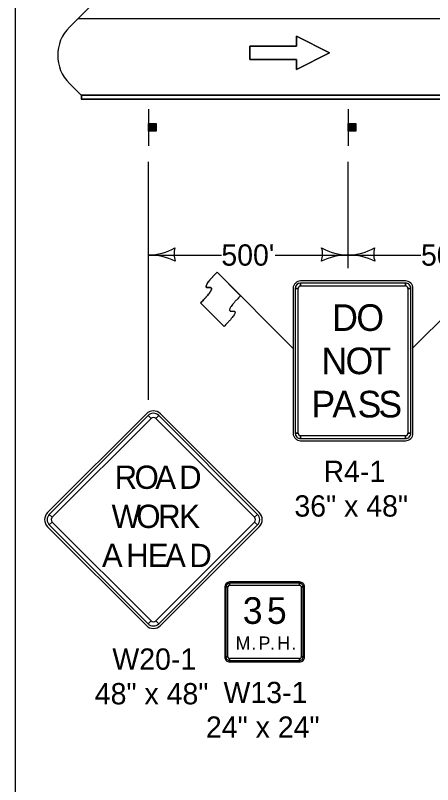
# Model space of a CAD drawing. Extents: x -2134934 to -2122394, y -2139046 to -2137036.
# Drawn here: x -2130232 to -2129918, y -2138183 to -2137605 of the extents above; entities that cross this region are included whole.
import ezdxf

# ---------------------------------------------------------------- set-up
doc = ezdxf.new("R2010")
doc.units = 0
for name, color, linetype in [('Barrier', 7, 'Continuous'), ('BridgeSuperStructureExisting', 7, 'Continuous'), ('Default', 7, 'Continuous'), ('DsnShtPlotIdentification', 7, 'Continuous'), ('TC_Barrier', 7, 'Continuous')]:
    doc.layers.add(name, color=color, linetype=linetype)

msp = doc.modelspace()

# ---------------------------------------------------------------- linework, layer by layer
at = {"layer": 'Barrier'}
for p, q in [((-2130023.11, -2137855.42), (-2130080.45, -2137798.12)), ((-2130080.45, -2137798.12), (-2130062.76, -2137815.8)), ((-2129933.82, -2137855.42), (-2129876.5, -2137798.11)), ((-2129938.87, -2137804.67), (-2130017.62, -2137804.67)), ((-2130017.62, -2137808.42), (-2130017.62, -2137806.23)), ((-2129938.87, -2137806.23), (-2129938.87, -2137808.42)), ((-2130023.24, -2137810.29), (-2130023.24, -2137919.04)), ((-2130021.68, -2137810.29), (-2130019.49, -2137810.29)), ((-2129936.99, -2137810.29), (-2129934.81, -2137810.29)), ((-2129933.24, -2137919.04), (-2129933.24, -2137810.29)), ((-2130075.13, -2137838.79), (-2130092.81, -2137821.12)), ((-2130133.53, -2137904.4), (-2130207.78, -2137978.64)), ((-2130132.2, -2137905.72), (-2130129.99, -2137907.93)), ((-2130126.46, -2137907.93), (-2130124.25, -2137905.72)), ((-2130048.68, -2137978.64), (-2130122.92, -2137904.4)), ((-2130019.49, -2137919.04), (-2130021.68, -2137919.04)), ((-2130017.62, -2137923.1), (-2130017.62, -2137920.91)), ((-2129938.87, -2137920.91), (-2129938.87, -2137923.1)), ((-2129934.81, -2137919.04), (-2129936.99, -2137919.04)), ((-2130017.62, -2137924.66), (-2129938.87, -2137924.66)), ((-2130204.24, -2137982.18), (-2130206.45, -2137979.97)), ((-2130050, -2137979.97), (-2130052.21, -2137982.18)), ((-2130206.45, -2137987.92), (-2130204.24, -2137985.71)), ((-2130052.21, -2137985.71), (-2130050, -2137987.92)), ((-2130207.78, -2137989.25), (-2130133.53, -2138063.5)), ((-2130122.92, -2138063.5), (-2130048.68, -2137989.25)), ((-2130018.46, -2138030.77), (-2130070.95, -2138030.77)), ((-2130070.95, -2138033.27), (-2130070.95, -2138031.71)), ((-2130018.46, -2138031.71), (-2130018.46, -2138033.27)), ((-2130074.7, -2138034.52), (-2130074.7, -2138087.02)), ((-2130073.77, -2138034.52), (-2130072.2, -2138034.52)), ((-2130017.21, -2138034.52), (-2130015.64, -2138034.52)), ((-2130014.71, -2138087.02), (-2130014.71, -2138034.52)), ((-2130129.99, -2138059.96), (-2130132.2, -2138062.17)), ((-2130124.25, -2138062.17), (-2130126.46, -2138059.96)), ((-2130072.2, -2138087.02), (-2130073.77, -2138087.02)), ((-2130070.95, -2138089.83), (-2130070.95, -2138088.27)), ((-2130070.95, -2138090.77), (-2130018.46, -2138090.77)), ((-2130018.46, -2138088.27), (-2130018.46, -2138089.83)), ((-2130015.64, -2138087.02), (-2130017.21, -2138087.02))]:
    msp.add_line(p, q, dxfattribs=at)
for points in [[(-2129938.87, -2137806.23), (-2130017.62, -2137806.23), (-2130017.62, -2137808.42), (-2129938.87, -2137808.42), (-2129938.87, -2137806.23)], [(-2130021.68, -2137810.29), (-2130021.68, -2137919.04), (-2130019.49, -2137919.04), (-2130019.49, -2137810.29), (-2130021.68, -2137810.29)], [(-2129934.81, -2137919.04), (-2129934.81, -2137810.29), (-2129936.99, -2137810.29), (-2129936.99, -2137919.04), (-2129934.81, -2137919.04)], [(-2130132.2, -2137905.72), (-2130206.45, -2137979.97), (-2130204.24, -2137982.18), (-2130129.99, -2137907.93), (-2130132.2, -2137905.72)], [(-2130050, -2137979.97), (-2130124.25, -2137905.72), (-2130126.46, -2137907.93), (-2130052.21, -2137982.18), (-2130050, -2137979.97)], [(-2130017.62, -2137923.1), (-2129938.87, -2137923.1), (-2129938.87, -2137920.91), (-2130017.62, -2137920.91), (-2130017.62, -2137923.1)], [(-2130206.45, -2137987.92), (-2130132.2, -2138062.17), (-2130129.99, -2138059.96), (-2130204.24, -2137985.71), (-2130206.45, -2137987.92)], [(-2130124.25, -2138062.17), (-2130050, -2137987.92), (-2130052.21, -2137985.71), (-2130126.46, -2138059.96), (-2130124.25, -2138062.17)], [(-2130018.46, -2138031.71), (-2130070.95, -2138031.71), (-2130070.95, -2138033.27), (-2130018.46, -2138033.27), (-2130018.46, -2138031.71)], [(-2130073.77, -2138034.52), (-2130073.77, -2138087.02), (-2130072.2, -2138087.02), (-2130072.2, -2138034.52), (-2130073.77, -2138034.52)], [(-2130015.64, -2138087.02), (-2130015.64, -2138034.52), (-2130017.21, -2138034.52), (-2130017.21, -2138087.02), (-2130015.64, -2138087.02)], [(-2130070.95, -2138089.83), (-2130018.46, -2138089.83), (-2130018.46, -2138088.27), (-2130070.95, -2138088.27), (-2130070.95, -2138089.83)]]:
    msp.add_lwpolyline(points, close=True, dxfattribs=at)
for centre, radius, start, end in [((-2130017.62, -2137810.29), 5.62, 90.00021, 179.99985), ((-2130017.62, -2137810.29), 4.06, 90.00021, 179.99985), ((-2129938.87, -2137810.29), 5.62, 0, 90.00021), ((-2129938.87, -2137810.29), 4.06, 0, 90.00021), ((-2130017.62, -2137810.29), 1.87, 90.00021, 179.99985), ((-2129938.87, -2137810.29), 1.87, 0, 90.00021), ((-2130128.23, -2137909.7), 7.5, 44.99999, 134.99974), ((-2130128.23, -2137909.7), 5.62, 44.99999, 134.99974), ((-2130128.23, -2137909.7), 2.5, 44.99999, 134.99974), ((-2130017.62, -2137919.04), 5.62, 179.99985, 270.00006), ((-2130017.62, -2137919.04), 4.06, 179.99985, 270.00006), ((-2130017.62, -2137919.04), 1.87, 179.99985, 270.00006), ((-2129938.87, -2137919.04), 5.62, 270.00006, 0.00027), ((-2129938.87, -2137919.04), 4.06, 270.00006, 0.00027), ((-2129938.87, -2137919.04), 1.87, 270.00006, 0.00027), ((-2130202.47, -2137983.95), 7.5, 134.99974, 224.99995), ((-2130202.47, -2137983.95), 5.62, 134.99974, 224.99995), ((-2130053.98, -2137983.95), 5.62, 315.00016, 44.9998), ((-2130053.98, -2137983.95), 7.5, 315.00016, 44.9998), ((-2130202.47, -2137983.95), 2.5, 134.99974, 224.99995), ((-2130053.98, -2137983.95), 2.5, 315.00016, 44.9998), ((-2130070.95, -2138034.52), 3.75, 90.00021, 179.99985), ((-2130070.95, -2138034.52), 2.81, 90.00021, 179.99985), ((-2130070.95, -2138034.52), 1.25, 90.00021, 179.99985), ((-2130018.46, -2138034.52), 3.75, 0, 90.00021), ((-2130018.46, -2138034.52), 2.81, 0, 90.00021), ((-2130018.46, -2138034.52), 1.25, 0, 90.00021), ((-2130128.23, -2138058.19), 5.62, 224.99995, 315.00016), ((-2130128.23, -2138058.19), 2.5, 224.99995, 315.00016), ((-2130128.23, -2138058.19), 7.5, 224.99995, 315.00016), ((-2130070.95, -2138087.02), 3.75, 179.99985, 270.00006), ((-2130070.95, -2138087.02), 2.81, 179.99985, 270.00006), ((-2130070.95, -2138087.02), 1.25, 179.99985, 270.00006), ((-2130018.46, -2138087.02), 3.75, 270.00006, 0.00027), ((-2130018.46, -2138087.02), 2.81, 270.00006, 0.00027), ((-2130018.46, -2138087.02), 1.25, 270.00006, 0.00027)]:
    msp.add_arc(centre, radius, start, end, dxfattribs=at)
for points in [[(-2130092.81, -2137821.12), (-2130080.44, -2137808.74), (-2130092.82, -2137810.51), (-2130080.45, -2137798.12)], [(-2130062.76, -2137815.8), (-2130075.13, -2137828.19), (-2130062.76, -2137826.41), (-2130075.13, -2137838.79)]]:
    msp.add_open_spline(points, degree=2, dxfattribs=at)
at = {"layer": 'BridgeSuperStructureExisting'}
for p, q in [((-2130173.78, -2137596.37), (-2130191.36, -2137613.95)), ((-2130173.79, -2137596.38), (-2130191.36, -2137613.95)), ((-2130191.36, -2137656.37), (-2130182.57, -2137665.16)), ((-2130191.36, -2137656.38), (-2130182.57, -2137665.16)), ((-2130182.57, -2137665.16), (-2128870.12, -2137665.16)), ((-2130131.95, -2137675.66), (-2130131.95, -2137703.16)), ((-2129981.95, -2137675.66), (-2129981.95, -2137703.16)), ((-2130131.54, -2137692.11), (-2130131.54, -2137686.52)), ((-2130131.26, -2137686.52), (-2130131.26, -2137692.11)), ((-2130130.99, -2137692.11), (-2130130.99, -2137686.52)), ((-2130130.73, -2137686.52), (-2130130.73, -2137692.11)), ((-2130130.51, -2137692.11), (-2130130.51, -2137686.52)), ((-2130130.3, -2137686.52), (-2130130.3, -2137692.11)), ((-2130129.96, -2137692.11), (-2130129.96, -2137686.52)), ((-2130129.7, -2137686.52), (-2130129.7, -2137692.11)), ((-2130129.47, -2137692.11), (-2130129.49, -2137686.52)), ((-2130129.16, -2137686.52), (-2130129.16, -2137692.11)), ((-2130128.78, -2137692.11), (-2130128.78, -2137686.52)), ((-2130128.35, -2137686.52), (-2130128.35, -2137692.11)), ((-2130128.12, -2137692.11), (-2130128.14, -2137686.52)), ((-2130127.71, -2137686.52), (-2130127.69, -2137692.11)), ((-2130127.49, -2137692.11), (-2130127.49, -2137686.52)), ((-2130127.17, -2137686.52), (-2130127.17, -2137692.11)), ((-2130126.94, -2137692.11), (-2130126.94, -2137686.52)), ((-2130126.62, -2137686.52), (-2130126.62, -2137692.11)), ((-2129981.54, -2137692.11), (-2129981.54, -2137686.52)), ((-2129981.26, -2137686.52), (-2129981.26, -2137692.11)), ((-2129980.99, -2137692.11), (-2129980.99, -2137686.52)), ((-2129980.73, -2137686.52), (-2129980.73, -2137692.11)), ((-2129980.51, -2137692.11), (-2129980.51, -2137686.52)), ((-2129980.3, -2137686.52), (-2129980.3, -2137692.11)), ((-2129979.96, -2137692.11), (-2129979.96, -2137686.52)), ((-2129979.7, -2137686.52), (-2129979.7, -2137692.11)), ((-2129979.47, -2137692.11), (-2129979.49, -2137686.52)), ((-2129979.16, -2137686.52), (-2129979.16, -2137692.11)), ((-2129978.78, -2137692.11), (-2129978.78, -2137686.52)), ((-2129978.35, -2137686.52), (-2129978.35, -2137692.11)), ((-2129978.12, -2137692.11), (-2129978.14, -2137686.52)), ((-2129977.71, -2137686.52), (-2129977.69, -2137692.11)), ((-2129977.49, -2137692.11), (-2129977.49, -2137686.52)), ((-2129977.17, -2137686.52), (-2129977.17, -2137692.11)), ((-2129976.94, -2137692.11), (-2129976.94, -2137686.52)), ((-2129976.62, -2137686.52), (-2129976.62, -2137692.11)), ((-2130131.95, -2137893.97), (-2130131.95, -2137715.16)), ((-2129981.95, -2137795.16), (-2129981.95, -2137715.16)), ((-2130131.95, -2137785.16), (-2130077.2, -2137785.16)), ((-2130036.7, -2137785.16), (-2129981.95, -2137785.16)), ((-2129981.95, -2137785.16), (-2129927.2, -2137785.16))]:
    msp.add_line(p, q, dxfattribs=at)
for points in [[(-2130055.82, -2137628.32), (-2130055.82, -2137638.32), (-2130020.82, -2137638.32), (-2130020.82, -2137645.82), (-2129995.82, -2137633.32), (-2130020.82, -2137620.82), (-2130020.82, -2137628.32)], [(-2130131.86, -2137692.11), (-2130131.86, -2137686.48), (-2130126.23, -2137686.48), (-2130126.23, -2137692.11)], [(-2129981.86, -2137692.11), (-2129981.86, -2137686.48), (-2129976.23, -2137686.48), (-2129976.23, -2137692.11)]]:
    msp.add_lwpolyline(points, close=True, dxfattribs=at)
msp.add_lwpolyline([(-2130020.82, -2137628.32), (-2130020.82, -2137620.82), (-2129995.82, -2137633.32), (-2130020.82, -2137645.82), (-2130020.82, -2137638.32), (-2130055.82, -2137638.32), (-2130055.82, -2137628.32), (-2130020.82, -2137628.32)], dxfattribs=at)
for centre, radius, start, end in [((-2130170.14, -2137635.16), 30, 135, 225), ((-2130170.14, -2137635.16), 30, 135, 225), ((-2130132.71, -2137742.67), 42.5, 271.0176, 299.07249), ((-2130096.33, -2137784.54), 16.42, 163.26665, 198.73335), ((-2130017.57, -2137784.54), 16.42, 341.26665, 16.73335), ((-2129981.2, -2137742.67), 42.5, 240.92751, 268.9824), ((-2129982.71, -2137742.67), 42.5, 271.0176, 299.07249), ((-2129946.33, -2137784.54), 16.42, 163.26665, 198.73335), ((-2130131.22, -2137827.65), 42.5, 62.92751, 90.9824), ((-2129982.68, -2137827.65), 42.5, 89.0176, 117.07249), ((-2129981.22, -2137827.65), 42.5, 62.92751, 90.9824)]:
    msp.add_arc(centre, radius, start, end, dxfattribs=at)
at = {"layer": 'Default'}
msp.add_lwpolyline([(-2130231.95, -2137035.95), (-2127096.96, -2137035.95), (-2127096.96, -2139045.94), (-2130231.95, -2139045.94)], close=True, dxfattribs=at)
at = {"layer": 'DsnShtPlotIdentification'}
for p, q in [((-2129531.95, -2137607.66), (-2130184.45, -2137607.66)), ((-2129535.12, -2137665.16), (-2130182.57, -2137665.16)), ((-2130182.57, -2137665.16), (-2130182.57, -2137668.16)), ((-2130182.57, -2137668.16), (-2129497.55, -2137668.16)), ((-2130181.95, -2137665.16), (-2128681.95, -2137665.16)), ((-2130181.95, -2137668.16), (-2130181.95, -2137665.16))]:
    msp.add_line(p, q, dxfattribs=at)
for points in [[(-2128870.12, -2137665.16), (-2130182.57, -2137665.16)], [(-2128870.12, -2137668.16), (-2130182.57, -2137668.16)]]:
    msp.add_lwpolyline(points, dxfattribs=at)
at = {"layer": 'TC_Barrier'}
msp.add_line((-2130092.81, -2137821.12), (-2130075.13, -2137838.79), dxfattribs=at)
for points in [[(-2130080.45, -2137798.12), (-2130092.82, -2137810.51), (-2130080.44, -2137808.74), (-2130092.81, -2137821.12)], [(-2130062.76, -2137815.8), (-2130075.13, -2137828.19), (-2130062.76, -2137826.41), (-2130075.13, -2137838.79)]]:
    msp.add_open_spline(points, degree=2, dxfattribs=at)

# ---------------------------------------------------------------- texts
at = {"layer": 'Barrier'}
for s, height, p in [('D', 20, (-2129993.87, -2137842.17)), ('O', 20, (-2129975.74, -2137842.17)), ('O', 20, (-2129983.87, -2137874.67)), ('N', 20, (-2130001.99, -2137874.67)), ('T', 20, (-2129966.06, -2137874.67)), ('P', 20, (-2130009.51, -2137907.17)), ('A', 20, (-2129993.82, -2137907.17)), ('S', 20, (-2129974.85, -2137907.17)), ('S', 20, (-2129959.17, -2137907.17)), ('R4-1', 16, (-2130000.41, -2137955.66)), ('R', 17.5, (-2130157.39, -2137960.82)), ('O', 17.5, (-2130142.38, -2137960.82)), ('A', 17.5, (-2130126.83, -2137960.82)), ('D', 17.5, (-2130108.95, -2137960.82)), ('36" x 48"', 16, (-2130022.31, -2137981.66)), ('W', 17.5, (-2130159.67, -2137990.2)), ('O', 17.5, (-2130141.08, -2137990.2)), ('R', 17.5, (-2130124.67, -2137990.2)), ('K', 17.5, (-2130108.81, -2137990.2)), ('A', 17.5, (-2130166.95, -2138019.57)), ('H', 17.5, (-2130148.74, -2138019.57)), ('E', 17.5, (-2130132.51, -2138019.57)), ('A', 17.5, (-2130119.47, -2138019.57)), ('D', 17.5, (-2130101.26, -2138019.57)), ('3', 20, (-2130061.09, -2138062.23)), ('5', 20, (-2130042.97, -2138062.23)), ('M', 10, (-2130066.48, -2138081.71)), ('P', 10, (-2130049.23, -2138081.71)), ('H', 10, (-2130035.11, -2138081.71)), ('W20-1', 16, (-2130159.08, -2138096.69)), ('.', 10, (-2130054.68, -2138081.71)), ('.', 10, (-2130040.57, -2138081.71)), ('.', 10, (-2130024.64, -2138081.71)), ('48" x 48"', 16, (-2130172.29, -2138122.69)), ('W13-1', 16, (-2130075.56, -2138121.77)), ('24" x 24"', 16, (-2130088.77, -2138147.77))]:
    msp.add_text(s, height=height, dxfattribs=at).set_placement(p)
at = {"layer": 'BridgeSuperStructureExisting'}
for p in [(-2130077.2, -2137793.16), (-2129927.2, -2137793.16)]:
    msp.add_text("500'", height=16, dxfattribs=at).set_placement(p)

doc.saveas('drawing.dxf')
